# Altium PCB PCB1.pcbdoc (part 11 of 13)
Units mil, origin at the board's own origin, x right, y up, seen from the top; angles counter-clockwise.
Board outline 5895.51 x 5895.51 mil, 8 copper layers (Top Layer, L2_GND1, L3_SIG1, L4_GND2, L5_PWR, L6_SIG2, L7_GND3, Bottom Layer), stack 63.761 mil thick; 673 components, 558 nets, 2797 pads, 1861 vias.
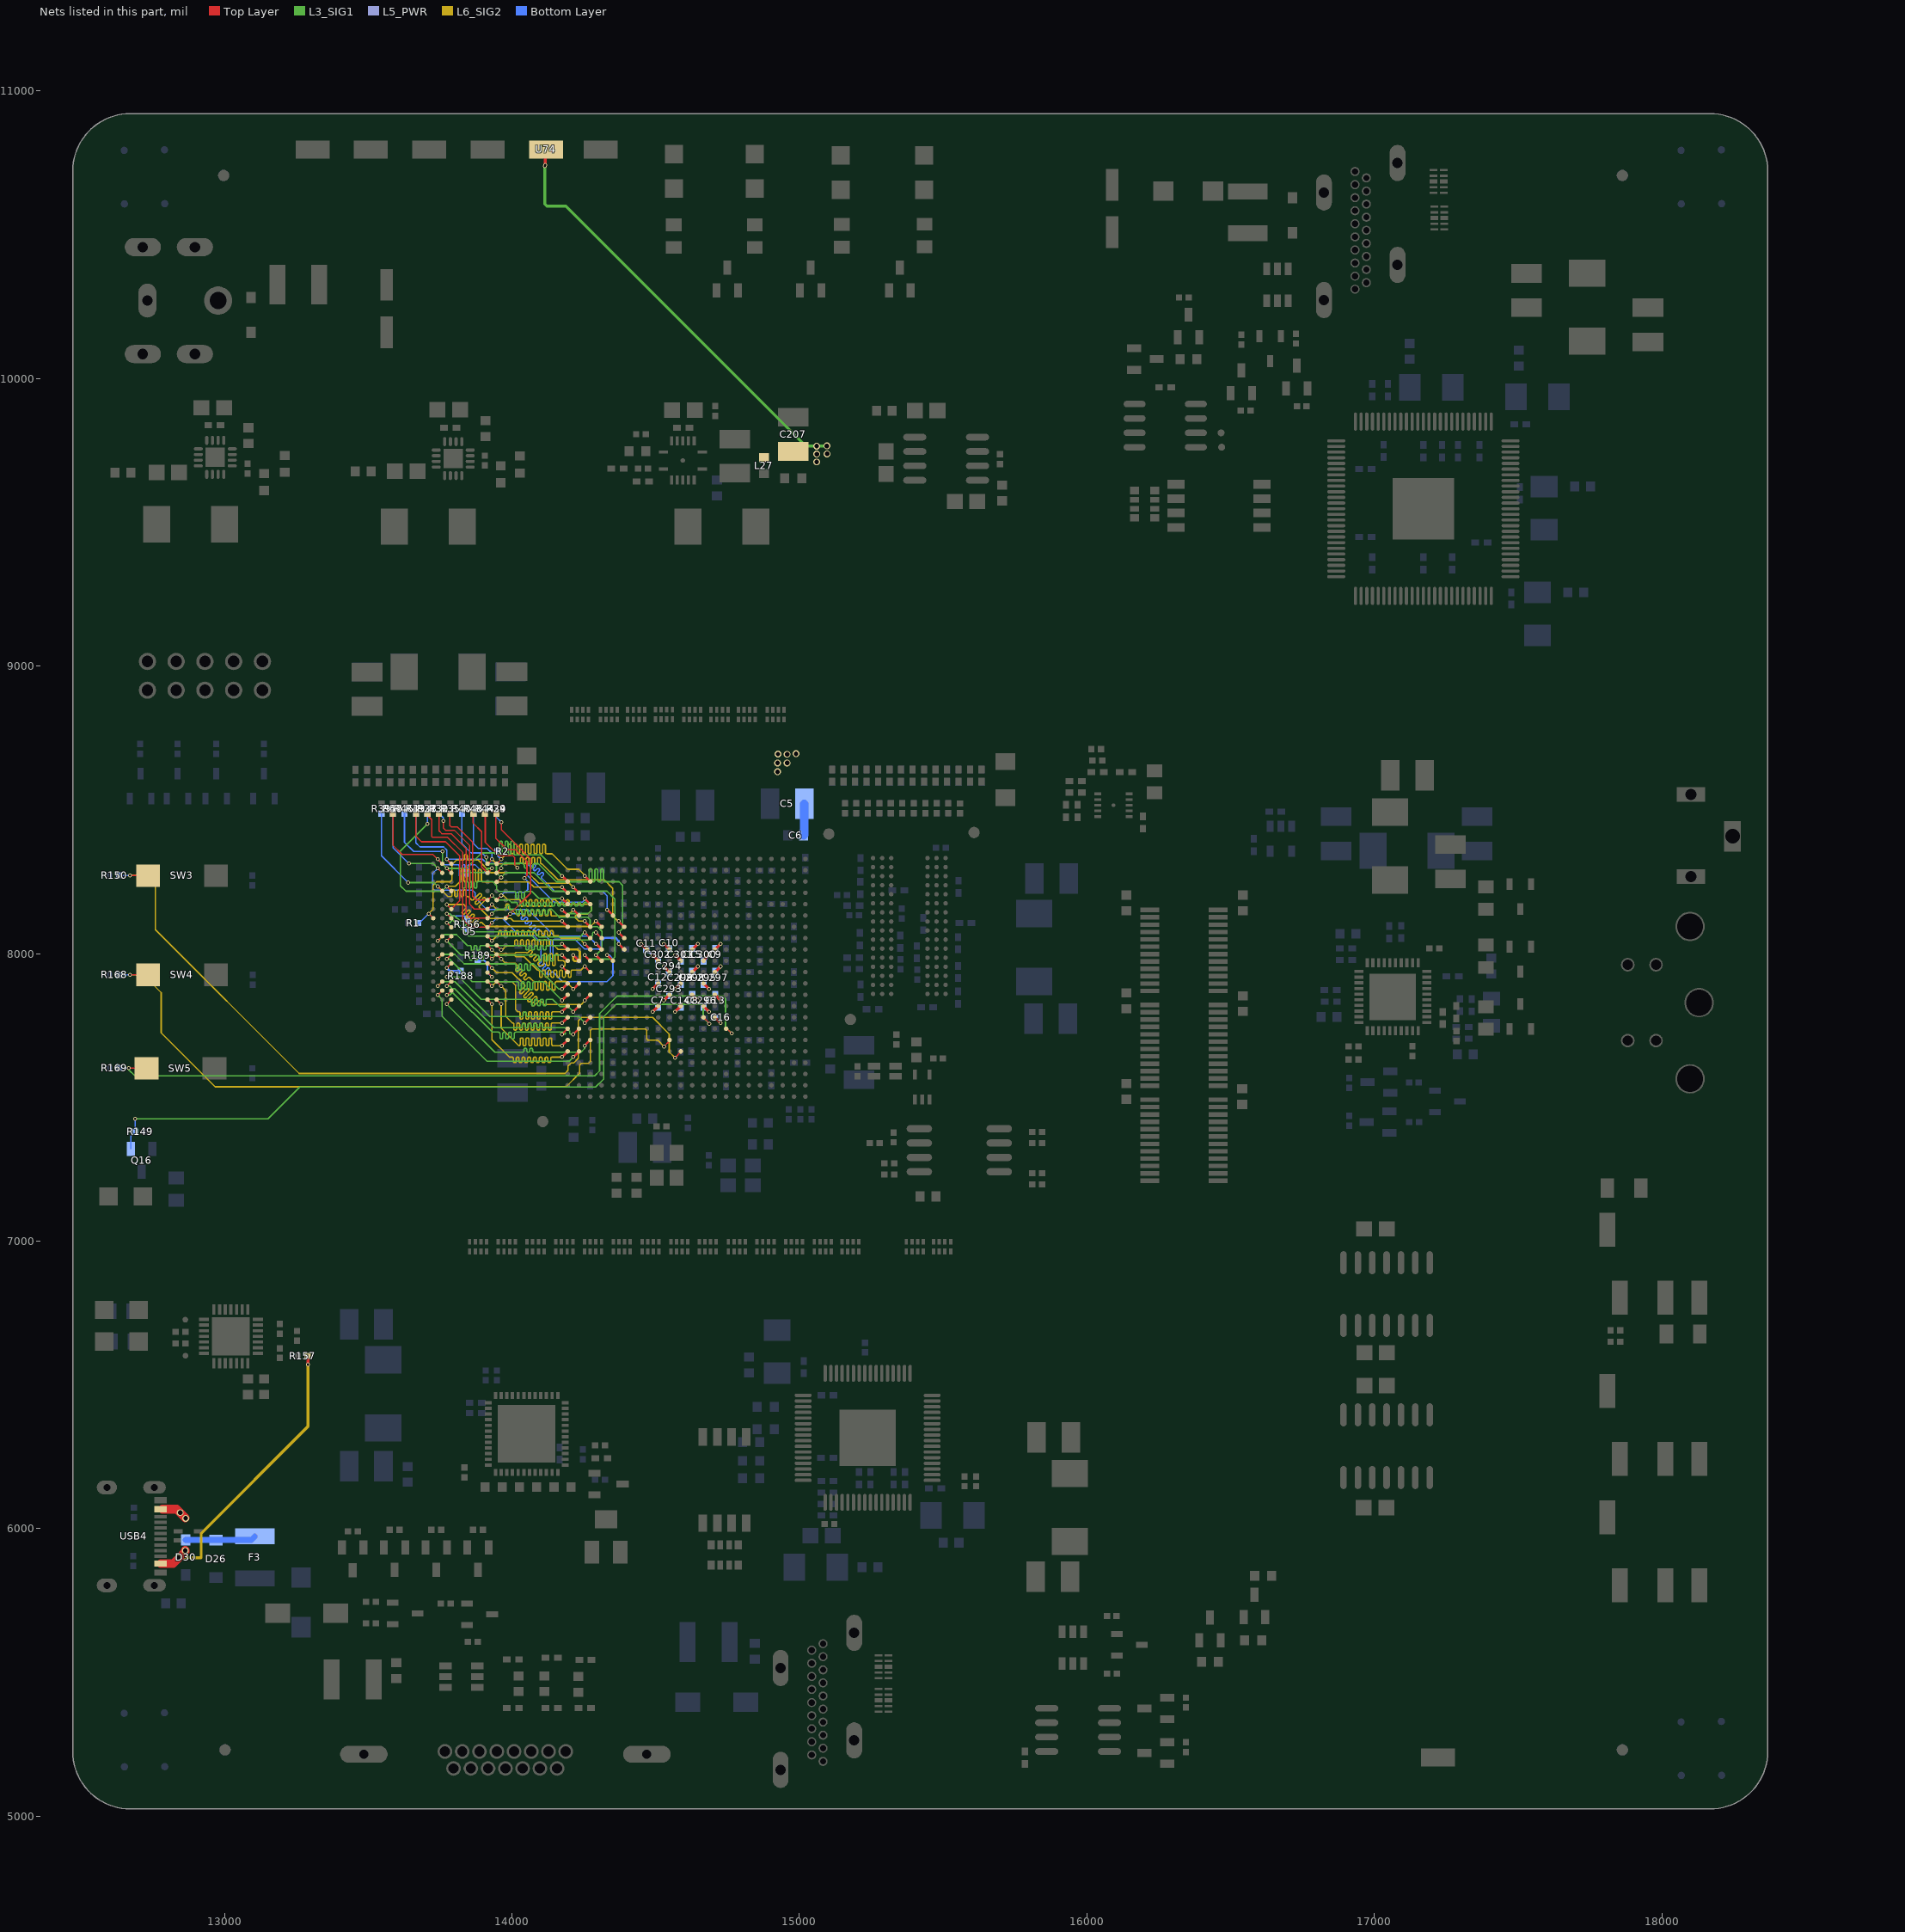
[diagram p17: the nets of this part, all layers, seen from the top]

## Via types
v1: diameter 23.62, hole 15.75, Top Layer to Bottom Layer, 621 vias
v2: diameter 13.8, hole 7.9, Top Layer to Bottom Layer, 567 vias
v3: diameter 13.78, hole 7.87, Top Layer to Bottom Layer, 529 vias
v4: diameter 13.78, hole 7.9, Top Layer to Bottom Layer, 114 vias
v5: diameter 15.75, hole 7.87, Top Layer to Bottom Layer, 16 vias
v6: diameter 24, hole 12, Top Layer to Bottom Layer, 10 vias
v7: diameter 11.81, hole 7.87, Top Layer to Bottom Layer, 4 vias

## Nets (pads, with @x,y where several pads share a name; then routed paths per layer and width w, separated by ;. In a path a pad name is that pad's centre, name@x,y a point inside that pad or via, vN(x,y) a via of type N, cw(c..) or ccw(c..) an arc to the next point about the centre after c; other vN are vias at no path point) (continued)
UP_A5: R40.1 U5.P2 U8.K3 | length 1120.5
  Top Layer w4.7: U5.P2@13946.85,8249.23 v2(13962.59,8264.98)
  Top Layer w7.9: v2(14253.04,7994.73) U8.K3@14272.71,7975.06
  L3_SIG1 w5: v3(13911.36,8335) 13911.36,8319 13918.36,8312 13942.36,8312 13946.36,8308 13946.36,8281.21 v2(13962.59,8264.98) 13978.85,8281.23 14077.44,8281.23 14141.74,8216.93 14330.9,8216.93 14358.3,8189.53 14358.3,7988.4 14350.8,7980.91 14266.86,7980.91 v2(14253.04,7994.73)
  Bottom Layer w4.7: R40.1@13826.36,8486.96 13826.36,8382 13858.36,8350 13896.36,8350 v3(13911.36,8335)
UP_A6: R47.1 U5.R8 U8.J4 | length 1090.5
  Top Layer w4.7: v2(13742.12,8296.47) U5.R8@13757.87,8280.72
  Top Layer w7.9: v2(14292.41,8034.1) U8.J4@14312.08,8014.43
  L3_SIG1 w5: v3(13642.36,8313) 13725.59,8313 v2(13742.12,8296.47)
  Bottom Layer w4.7: R47.1@13586.36,8486.96 13586.36,8369 v3(13642.36,8313) ; v2(13742.12,8296.47) 13723.81,8278.15 13723.81,8224.74 13728.02,8220.53 13862.63,8220.53 13872.74,8210.42 13872.74,8193.68 13913.5,8152.91 14055.84,8152.91 14148.13,8060.62 14265.89,8060.62 v2(14292.41,8034.1)
UP_A7: R44.1 U5.R2 U8.H6 | length 1263.4
  Top Layer w4.7: R44.1@13906.36,8486.96 13907.36,8485.96 13907.36,8387 13953.43,8340.92 14002.95,8340.92 14009.36,8334.51 14009.36,8308 v3(14019.36,8298) ; U5.R2@13946.85,8280.72 v2(13962.59,8296.47)
  Top Layer w7.9: v2(14371.15,8073.47) U8.H6@14390.82,8053.8
  L3_SIG1 w5: v2(13962.59,8296.47) 13962.59,8304.44 13972.37,8314.22 14036.83,8314.22 14043.58,8307.47 14043.58,8302.15 ccw(c14048.58,8302.15) 14053.58,8302.15 14053.58,8307.47 cw(c14058.58,8307.47) 14063.58,8307.47 14063.58,8302.15 ccw(c14068.58,8302.15) 14073.58,8302.15 14073.58,8307.47 cw(c14078.58,8307.47) 14078.58,8312.47 14092.31,8312.47 14155.08,8249.7 14263.59,8249.7 ccw(c14263.59,8254.7) 14268.59,8254.7 14268.59,8289.55 cw(c14273.59,8289.55) 14278.59,8289.55 14278.59,8254.7 ccw(c14283.59,8254.7) 14288.59,8254.7 14288.59,8289.55 cw(c14293.59,8289.55) 14298.59,8289.55 14298.59,8254.7 ccw(c14303.59,8254.7) 14308.59,8254.7 14308.59,8289.55 cw(c14313.59,8289.55) 14318.59,8289.55 14318.59,8254.7 ccw(c14323.59,8254.7) 14323.59,8249.7 14372.66,8249.7 14385.36,8237 14385.36,8087.68 v2(14371.15,8073.47) ; 14003.34,8314.01 v3(14019.36,8298)
  Bottom Layer w4.7: v3(14019.36,8298) v3@14019.36,8301
UP_A8: R50.1 U5.T8 U8.E3 | length 1069.8
  Top Layer w4.7: R50.1@13586.36,8486.96 13586.36,8377 13618.36,8345 13725.09,8345 v2(13742.12,8327.97) U5.T8@13757.87,8312.22
  Top Layer w7.9: v2(14253.04,8191.57) U8.E3@14272.71,8171.9
  Bottom Layer w4.7: v2(13742.12,8327.97) 13760.76,8309.33 13812.12,8309.33 cw(c13812.12,8304.33) 13817.12,8304.33 13817.12,8271.86 ccw(c13822.12,8271.86) 13827.12,8271.86 13827.12,8304.33 cw(c13832.12,8304.33) 13837.12,8304.33 13837.12,8271.86 ccw(c13842.12,8271.86) 13847.12,8271.86 13847.12,8304.33 cw(c13852.12,8304.33) 13852.12,8309.33 13871.32,8309.33 13898.44,8282.21 14043.22,8282.21 14146.7,8178.72 14245.14,8178.72 14253.04,8186.62 v2(14253.04,8191.57)
UP_A9: R45.1 U5.R3 U8.E1 | length 1000.6
  Top Layer w4.7: R45.1@13866.36,8486.96 13865.36,8485.96 13865.36,8453.37 13894.36,8424.37 13894.36,8301.71 U5.R3@13915.35,8280.72 v2(13931.09,8296.47)
  Top Layer w7.9: v2(14174.29,8191.57) U8.E1@14193.96,8171.9
  L3_SIG1 w5: 13828.39,8245.17 ccw(c13823.39,8245.18) 13823.39,8250.18 13819.59,8253.97 13819.59,8273.91 13827.74,8282.05 13901.51,8282.05 13915.93,8296.47 v2(13931.09,8296.47) ; 13828.39,8245.17 13828.38,8232.68 ccw(c13833.38,8232.68) 13838.38,8232.68 13838.39,8245.17 cw(c13843.39,8245.17) 13848.39,8245.17 13848.38,8232.68 ccw(c13853.38,8232.67) 13858.38,8232.67 13858.39,8245.17 cw(c13863.39,8245.17) 13868.39,8245.17 13868.38,8232.67 ccw(c13873.38,8232.67) 13878.38,8232.67 13878.39,8245.17 cw(c13883.39,8245.17) 13883.39,8250.17 13933.49,8250.17 13947.54,8236.12 13947.54,8223.05 13954.35,8216.24 14008.61,8216.24 cw(c14008.61,8211.24) 14013.61,8211.24 14013.61,8195.7 ccw(c14018.61,8195.7) 14023.61,8195.7 14023.61,8211.24 cw(c14028.61,8211.24) 14033.61,8211.24 14033.61,8195.7 ccw(c14038.61,8195.7) 14043.61,8195.7 14043.61,8211.24 cw(c14048.61,8211.24) 14048.61,8216.24 14069.36,8216.24 14093.69,8191.91 14173.95,8191.91 v2(14174.29,8191.57)
UP_A10: R33.1 U5.L7 U8.G4 | length 1236.7
  Top Layer w4.7: R33.1@13666.36,8486.96 13666.36,8408 13685.36,8389 13768.77,8389 13818.36,8339.42 13818.36,8183.73 U5.L7@13789.37,8154.74 v2(13773.62,8170.48)
  Top Layer w7.9: v2(14292.41,8112.84) U8.G4@14312.08,8093.16
  L6_SIG2 w5: v2(13773.62,8170.48) 13833.18,8170.48 13839.56,8164.1 cw(c13836.03,8160.56) 13839.56,8157.03 13828.36,8145.82 ccw(c13831.89,8142.28) 13835.43,8138.75 13846.63,8149.95 cw(c13850.17,8146.42) 13853.71,8142.88 13842.5,8131.68 ccw(c13846.03,8128.14) 13849.57,8124.6 13860.78,8135.81 cw(c13864.31,8132.28) 13867.85,8128.74 13856.64,8117.53 ccw(c13860.18,8114) 13863.71,8110.46 13874.92,8121.67 cw(c13878.45,8118.13) 13881.99,8114.6 13870.78,8103.39 ccw(c13874.32,8099.86) 13877.85,8096.32 13889.06,8107.53 cw(c13892.6,8103.99) 13896.13,8107.53 13909.38,8094.28 14273.84,8094.28 v2(14292.41,8112.84)
UP_A11: R46.1 U5.R7 U8.C1 | length 1074.5
  Top Layer w4.7: v2(13773.62,8296.47) U5.R7@13789.37,8280.72
  Top Layer w7.9: v2(14174.29,8270.32) U8.C1@14193.96,8250.65
  L3_SIG1 w5: v3(13758.36,8355) 13758.36,8311.73 v2(13773.62,8296.47) 13840.82,8296.47 13894.36,8350 13945.05,8350 13951.5,8343.55 ccw(c13951.5,8348.55) 13956.5,8348.55 13956.5,8385.92 cw(c13961.5,8385.92) 13966.5,8385.92 13966.5,8348.55 ccw(c13971.5,8348.55) 13976.5,8348.55 13976.5,8385.92 cw(c13981.5,8385.92) 13986.5,8385.92 13986.5,8348.55 ccw(c13991.5,8348.55) 13996.5,8348.55 13996.5,8385.92 cw(c14001.5,8385.92) 14006.5,8385.92 14006.5,8348.55 ccw(c14011.5,8348.55) 14011.5,8343.55 14101.05,8343.55 v2(14174.29,8270.32)
  Bottom Layer w4.7: R46.1@13626.36,8486.96 13626.36,8387 13658.36,8355 v3(13758.36,8355)
UP_A12: R38.1 U5.N7 U8.D1 | length 1243.6
  Top Layer w4.7: v2(13773.62,8233.48) U5.N7@13789.37,8217.73
  Top Layer w7.9: v2(14174.29,8230.95) U8.D1@14193.96,8211.27
  L3_SIG1 w5: v3(13706.36,8451) 13612.36,8357 13612.36,8236 13631.36,8217 13757.15,8217 v2(13773.62,8233.48)
  L6_SIG2 w5: v2(13773.62,8233.48) 13774.44,8234.3 13803.58,8234.3 13818.74,8249.46 ccw(c13818.74,8254.46) 13823.74,8254.46 13823.74,8287.84 cw(c13828.74,8287.84) 13833.74,8287.84 13833.74,8254.46 ccw(c13838.74,8254.46) 13843.74,8254.46 13843.74,8287.84 cw(c13848.74,8287.84) 13853.74,8287.84 13853.74,8254.46 ccw(c13858.74,8254.46) 13863.74,8254.46 13863.74,8287.84 cw(c13868.74,8287.84) 13873.74,8287.84 13873.74,8254.46 ccw(c13878.74,8254.46) 13883.74,8254.46 13883.74,8287.84 cw(c13888.74,8287.84) 13893.74,8287.84 13893.74,8254.46 ccw(c13898.74,8254.46) 13898.74,8249.46 14058.14,8249.46 14076.65,8230.95 v2(14174.29,8230.95)
  Bottom Layer w4.7: v3(13706.36,8451) R38.1@13706.36,8486.96
UP_A13: R48.1 U5.T3 U8.G6 | length 985.5
  Top Layer w4.7: U5.T3@13915.35,8312.22 v2(13931.09,8327.97)
  Top Layer w7.9: v2(14371.15,8112.84) U8.G6@14390.82,8093.16
  L6_SIG2 w5: v2(13931.09,8327.97) 13947.19,8311.86 14024.13,8311.86 ccw(c14024.13,8316.86) 14029.13,8316.86 14029.13,8329.47 cw(c14034.13,8329.47) 14039.13,8329.47 14039.13,8316.86 ccw(c14044.13,8316.86) 14049.13,8316.86 14049.13,8329.47 cw(c14054.13,8329.47) 14059.13,8329.47 14059.13,8316.86 ccw(c14064.13,8316.86) 14069.13,8316.86 14069.13,8329.47 cw(c14074.13,8329.47) 14079.13,8329.47 14079.13,8316.86 ccw(c14084.13,8316.86) 14089.13,8316.86 14089.13,8329.47 cw(c14094.13,8329.47) 14099.13,8329.47 14099.13,8316.86 ccw(c14104.13,8316.86) 14104.13,8311.86 14104.98,8311.86 14160.43,8256.41 14321.57,8256.41 14350.95,8227.03 14350.95,8130.82 14368.93,8112.84 v2(14371.15,8112.84)
  Bottom Layer w4.7: R48.1@13866.36,8486.96 13866.36,8383 13883.36,8366 13913.36,8366 13930.36,8349 13930.36,8328.7 v2(13931.09,8327.97)
UP_A14: R49.1 U5.T7 U8.F5 | length 1034.6
  Top Layer w4.7: v2(13773.62,8327.97) U5.T7@13789.37,8312.22
  Top Layer w7.9: v2(14331.79,8152.21) U8.F5@14351.46,8132.53
  Bottom Layer w4.7: R49.1@13666.36,8486.96 13666.36,8385 13680.36,8371 13762.36,8371 13773.36,8360 13773.36,8328.23 v2(13773.62,8327.97) ; v2@13773.39,8328.34 13897.46,8328.34 13911.86,8313.94 14052.15,8313.94 14062.01,8304.08 ccw(c14065.55,8307.62) 14069.08,8304.08 14073.75,8308.75 cw(c14077.28,8305.21) 14080.82,8301.68 14076.15,8297.01 ccw(c14079.69,8293.48) 14083.23,8289.94 14087.89,8294.61 cw(c14091.43,8291.07) 14094.96,8287.53 14090.3,8282.87 ccw(c14093.83,8279.33) 14097.37,8275.8 14102.03,8280.46 cw(c14105.57,8276.93) 14109.1,8273.39 14104.44,8268.73 ccw(c14107.97,8265.19) 14104.44,8261.66 14149.72,8216.38 14316.07,8216.38 14331.63,8200.82 v2@14331.63,8152.66
UP_BA0: R34.1 U5.M2 U8.G3 | length 1189.9
  Top Layer w4.7: R34.1@13946.36,8486.96 13944.36,8484.96 13944.36,8401 13984.36,8361 14012.36,8361 14052.36,8321 14052.36,8272 v3(14043.36,8263) ; U5.M2@13946.85,8186.24 v2(13962.59,8201.99)
  Top Layer w7.9: v2(14253.04,8112.84) U8.G3@14272.71,8093.16
  L6_SIG2 w5: v2(13962.59,8201.99) 13970.78,8201.99 13985.02,8187.75 14024.81,8187.75 cw(c14024.81,8182.75) 14029.81,8182.75 14029.81,8169.4 ccw(c14034.81,8169.4) 14039.81,8169.4 14039.81,8182.75 cw(c14044.81,8182.75) 14049.81,8182.75 14049.81,8169.4 ccw(c14054.81,8169.4) 14059.81,8169.4 14059.81,8182.75 cw(c14064.81,8182.75) 14069.81,8182.75 14069.81,8169.4 ccw(c14074.81,8169.4) 14079.81,8169.4 14079.81,8182.75 cw(c14084.81,8182.75) 14089.81,8182.75 14089.81,8169.4 ccw(c14094.81,8169.4) 14099.81,8169.4 14099.81,8182.75 cw(c14104.81,8182.75) 14109.81,8182.75 14109.81,8169.4 ccw(c14114.81,8169.4) 14119.81,8169.4 14119.81,8182.75 cw(c14124.81,8182.75) 14129.81,8182.75 14129.81,8169.4 ccw(c14134.81,8169.4) 14139.81,8169.4 14139.81,8182.75 cw(c14144.81,8182.75) 14144.81,8187.75 14150.2,8187.75 14166.45,8171.49 14184.06,8171.49 ccw(c14184.06,8176.49) 14189.06,8176.49 14189.06,8182.15 cw(c14194.06,8182.15) 14199.06,8182.15 14199.06,8176.49 ccw(c14204.06,8176.49) 14204.06,8171.49 14272.05,8171.49 14275.53,8168.01 14275.53,8149.06 14264.47,8138 14227.5,8138 14220.55,8131.05 14220.55,8125.36 14233.07,8112.84 v2(14253.04,8112.84)
  Bottom Layer w4.7: v2(13962.59,8201.99) 13974.27,8213.66 14046.02,8213.66 14054.36,8222 14055.36,8222 14055.36,8251 v3(14043.36,8263)
UP_BA1: R39.1 U5.N8 U8.G1 | length 1166.6
  Top Layer w4.7: v2(13742.12,8233.48) U5.N8@13757.87,8217.73
  Top Layer w7.9: v2(14174.29,8112.84) U8.G1@14193.96,8093.16
  L3_SIG1 w5: v3(13639.36,8247) 13728.6,8247 v2(13742.12,8233.48)
  L6_SIG2 w5: v2(13742.12,8233.48) 13777.48,8198.11 13786.27,8198.11 ccw(c13786.27,8203.11) 13791.27,8203.11 13791.27,8216.33 cw(c13796.27,8216.33) 13801.27,8216.33 13801.27,8203.11 ccw(c13806.27,8203.11) 13811.27,8203.11 13811.27,8216.33 cw(c13816.27,8216.33) 13821.27,8216.33 13821.27,8203.11 ccw(c13826.27,8203.11) 13831.27,8203.11 13831.27,8216.33 cw(c13836.27,8216.33) 13841.27,8216.33 13841.27,8203.11 ccw(c13846.27,8203.11) 13846.27,8198.11 13848.63,8198.11 13859.3,8187.45 ccw(c13862.83,8190.99) 13866.37,8187.45 13886.01,8207.1 cw(c13889.55,8203.56) 13893.08,8200.02 13873.44,8180.38 ccw(c13876.98,8176.84) 13880.51,8173.31 13900.16,8192.95 cw(c13903.69,8189.42) 13907.23,8185.88 13887.58,8166.24 ccw(c13891.12,8162.7) 13887.58,8159.17 13924.31,8122.44 13996.19,8122.44 14005.35,8113.28 14173.85,8113.28 v2(14174.29,8112.84)
  Bottom Layer w4.7: R39.1@13546.36,8486.96 13546.36,8340 v3(13639.36,8247)
UP_BA2: R35.1 U5.M3 U8.F1 | length 1129.4
  Top Layer w4.7: R35.1@13786.36,8486.96 13784.36,8484.96 13784.36,8445 13788.36,8441 13809.41,8441 13863.36,8387.05 13863.36,8200 13877.12,8186.24 U5.M3@13915.35,8186.24 v2(13931.09,8201.99)
  Top Layer w7.9: v2(14174.29,8152.21) U8.F1@14193.96,8132.53
  L3_SIG1 w5: v2(13931.09,8201.99) 13947.21,8185.87 13990.64,8185.87 13998.54,8177.97 14014.14,8177.97 cw(c14014.14,8172.97) 14019.14,8172.97 14019.14,8170.27 ccw(c14024.14,8170.27) 14029.14,8170.27 14029.14,8172.97 cw(c14034.14,8172.97) 14039.14,8172.97 14039.14,8170.27 ccw(c14044.14,8170.27) 14049.14,8170.27 14049.14,8172.97 cw(c14054.14,8172.97) 14059.14,8172.97 14059.14,8170.27 ccw(c14064.14,8170.27) 14069.14,8170.27 14069.14,8172.97 cw(c14074.14,8172.97) 14079.14,8172.97 14079.14,8170.27 ccw(c14084.14,8170.27) 14089.14,8170.27 14089.14,8172.97 cw(c14094.14,8172.97) 14099.14,8172.97 14099.14,8170.27 ccw(c14104.14,8170.27) 14109.14,8170.27 14109.14,8172.97 cw(c14114.14,8172.97) 14119.14,8172.97 14119.14,8170.27 ccw(c14124.14,8170.27) 14129.14,8170.27 14129.14,8172.97 cw(c14134.14,8172.97) 14139.14,8172.97 14139.14,8170.27 ccw(c14144.14,8170.27) 14149.14,8170.27 14149.14,8172.97 cw(c14154.14,8172.97) 14159.14,8172.97 14159.14,8170.27 ccw(c14164.14,8170.27) 14169.14,8170.27 14169.14,8172.97 cw(c14174.14,8172.97) 14179.14,8172.97 14179.14,8170.27 ccw(c14184.14,8170.27) 14189.14,8170.27 14189.14,8172.97 cw(c14194.14,8172.97) 14199.14,8172.97 14199.14,8170.27 ccw(c14204.14,8170.27) 14209.14,8170.27 14209.14,8172.97 cw(c14214.14,8172.97) 14219.14,8172.97 14219.14,8170.27 ccw(c14224.14,8170.27) 14229.14,8170.27 14229.14,8172.97 cw(c14234.14,8172.97) 14239.14,8172.97 14239.14,8170.27 ccw(c14244.14,8170.27) 14249.14,8170.27 14249.14,8172.97 cw(c14254.14,8172.97) 14254.14,8177.97 14260.79,8177.97 14277.22,8161.54 14277.22,8150.8 14265.42,8139 14187.49,8139 v2(14174.29,8152.21)
UP_CAS: R30.1 U5.K3 U8.K4 | length 1245.6
  Top Layer w4.7: R30.1@13746.36,8486.96 13746.36,8427 13756.36,8417 13788.45,8417 13841.36,8364.1 13841.36,8139 13857.12,8123.24 U5.K3@13915.35,8123.24 v2(13931.09,8138.98)
  Top Layer w7.9: v2(14292.41,7994.73) U8.K4@14312.08,7975.06
  L3_SIG1 w5: v2(13931.09,8138.98) 13946.11,8154 13977.33,8154 ccw(c13977.33,8159) 13982.33,8159 13982.33,8163.53 cw(c13987.33,8163.53) 13992.33,8163.53 13992.33,8159 ccw(c13997.33,8159) 13997.33,8154 14010.61,8154 cw(c14010.61,8149) 14015.61,8149 14015.61,8140.88 ccw(c14020.61,8140.88) 14025.61,8140.88 14025.61,8149 cw(c14030.61,8149) 14035.61,8149 14035.61,8140.88 ccw(c14040.61,8140.88) 14045.61,8140.88 14045.61,8149 cw(c14050.61,8149) 14055.61,8149 14055.61,8140.88 ccw(c14060.61,8140.88) 14065.61,8140.88 14065.61,8149 cw(c14070.61,8149) 14075.61,8149 14075.61,8140.88 ccw(c14080.61,8140.88) 14085.61,8140.88 14085.61,8149 cw(c14090.61,8149) 14095.61,8149 14095.61,8140.88 ccw(c14100.61,8140.88) 14105.61,8140.88 14105.61,8149 cw(c14110.61,8149) 14115.61,8149 14115.61,8140.88 ccw(c14120.61,8140.88) 14125.61,8140.88 14125.61,8149 cw(c14130.61,8149) 14130.61,8154 14137.94,8154 14165.73,8126.21 14263.68,8126.21 14272.23,8117.66 14272.23,8099.97 14278.55,8093.65 14297.5,8093.65 14313.62,8077.53 14313.62,8015.94 v2(14292.41,7994.73)
  L3_SIG1 w7.9: 14165.73,8126.21 14165.85,8126.09
UP_CK+: R156.1 U5.J7 U8.H4 | length 703.9
  Top Layer w4.7: v2(13773.62,8107.49) U5.J7@13789.37,8091.75
  Top Layer w6.2: v2(14292.41,8073.47) U8.H4@14312.08,8053.8
  L3_SIG1 w4.2: v2(13773.62,8107.49) 13783.62,8107.49 13791.77,8115.64 13794.87,8115.64 13849.36,8061.15 14071.21,8061.15 14084.64,8047.72 14266.16,8047.72 14280.32,8061.88 14280.32,8071.28 14282.51,8073.47 v2(14292.41,8073.47)
  Bottom Layer w4: v2(13773.62,8107.49) 13783.62,8107.49 13791.77,8115.64 13800.09,8115.64 13831.07,8084.66 R156.1@13844.8,8084.66
UP_CK-: R156.2 U5.K7 U8.H3 | length 709
  Top Layer w4.7: v2(13773.62,8138.98) U5.K7@13789.37,8123.24
  Top Layer w6.2: v2(14253.04,8073.47) U8.H3@14272.71,8053.8
  L3_SIG1 w4.2: v2(13773.62,8138.98) 13783.62,8138.98 13791.77,8130.84 13801.16,8130.84 13818.13,8113.88 ccw(c13821.66,8117.41) 13825.2,8113.88 13828.07,8116.75 cw(c13831.61,8113.22) 13835.14,8109.68 13832.27,8106.81 ccw(c13835.8,8103.27) 13839.34,8099.74 13842.21,8102.61 cw(c13845.75,8099.08) 13849.29,8095.54 13846.41,8092.66 ccw(c13849.95,8089.13) 13846.41,8085.59 13856,8076 14077.01,8076 14095.01,8058 14237.05,8058 14252.52,8073.47 v2(14253.04,8073.47)
  Bottom Layer w4: v2(13773.62,8138.98) 13783.62,8138.98 13791.77,8130.84 13837.16,8130.84 13851.1,8116.9 13851.1,8112.22 13844.8,8118.51 R156.2@13844.8,8118.74
UP_CKE: R1.1 U5.K9 U8.D2 | length 831.2
  Top Layer w4.7: v2(13710.63,8138.98) U5.K9@13726.38,8123.24
  Top Layer w7.9: v2(14213.67,8230.95) U8.D2@14233.34,8211.27
  L6_SIG2 w5: v2(13710.63,8138.98) 13725.61,8153.97 13725.61,8237.22 13738.41,8250.02 13786.75,8250.02 ; 13786.87,8250.13 13792.01,8255.28 13792.01,8309.67 13807.39,8325.04 13829.61,8325.04 ccw(c13829.61,8330.04) 13834.61,8330.04 13834.61,8339.71 cw(c13839.61,8339.71) 13844.61,8339.71 13844.61,8330.04 ccw(c13849.61,8330.04) 13849.61,8325.04 13882.91,8325.04 13926.55,8281.4 14056.9,8281.4 14093.55,8244.75 14199.87,8244.75 v2(14213.67,8230.95)
  Bottom Layer w4.7: R1.1@13673.36,8106.34 13677.99,8106.34 v2(13710.63,8138.98)
UP_D0: U5.E3 U8.N3 | length 652.6
  Top Layer w4.7: U5.E3@13915.35,7965.76 v2(13931.09,7950.02)
  Top Layer w7.9: v2(14253.04,7837.27) U8.N3@14272.71,7856.94
  L6_SIG2 w5: v2(13931.09,7950.02) 13947.11,7934 14001.36,7934 14043.8,7891.56 cw(c14040.26,7888.02) 14043.8,7884.49 14028.32,7869.01 ccw(c14031.85,7865.47) 14035.39,7861.93 14050.87,7877.42 cw(c14054.4,7873.88) 14057.94,7870.35 14042.46,7854.86 ccw(c14045.99,7851.33) 14049.53,7847.79 14065.01,7863.27 cw(c14068.55,7859.74) 14072.08,7856.2 14056.6,7840.72 ccw(c14060.14,7837.19) 14063.67,7833.65 14079.15,7849.13 cw(c14082.69,7845.6) 14086.22,7842.06 14070.74,7826.58 ccw(c14074.28,7823.04) 14077.81,7819.51 14093.3,7834.99 cw(c14096.83,7831.46) 14100.37,7834.99 14112,7823.36 14241.71,7823.36 14253.04,7834.68 v2(14253.04,7837.27)
UP_D1: U5.F7 U8.N1 | length 650.5
  Top Layer w4.7: v2(13773.62,7981.52) U5.F7@13789.37,7997.26
  Top Layer w7.9: v2(14174.29,7837.27) U8.N1@14193.96,7856.94
  L3_SIG1 w5: v2(13773.62,7981.52) 13782.25,7981.52 13861.7,7902.06 14018.12,7902.06 cw(c14018.12,7897.06) 14023.12,7897.06 14023.12,7879.44 ccw(c14028.12,7879.44) 14033.12,7879.44 14033.12,7897.06 cw(c14038.12,7897.06) 14043.12,7897.06 14043.12,7879.44 ccw(c14048.12,7879.44) 14053.12,7879.44 14053.12,7897.06 cw(c14058.12,7897.06) 14063.12,7897.06 14063.12,7879.44 ccw(c14068.12,7879.44) 14073.12,7879.44 14073.12,7897.06 cw(c14078.12,7897.06) 14078.12,7902.06 14109.49,7902.06 v2(14174.29,7837.27)
UP_D2: U5.F2 U8.M2 | length 632.2
  Top Layer w4.7: U5.F2@13946.85,7997.26 v2(13962.59,7981.52)
  Top Layer w7.9: v2(14213.67,7876.62) U8.M2@14233.34,7896.3
  L6_SIG2 w5: v2(13962.59,7981.52) 13962.84,7981.52 13978.36,7966 14012.36,7966 14020,7958.35 cw(c14016.47,7954.82) 14020,7951.28 14014.62,7945.9 ccw(c14018.15,7942.36) 14021.69,7938.83 14027.07,7944.21 cw(c14030.61,7940.68) 14034.15,7937.14 14028.76,7931.75 ccw(c14032.29,7928.22) 14035.83,7924.68 14041.22,7930.07 cw(c14044.75,7926.53) 14048.29,7923 14042.9,7917.61 ccw(c14046.44,7914.08) 14049.97,7910.54 14055.36,7915.93 cw(c14058.89,7912.39) 14062.43,7915.93 14075.36,7903 cw(c14075.36,7898) 14080.36,7898 14080.36,7877.75 ccw(c14085.36,7877.75) 14090.36,7877.75 14090.36,7898 cw(c14095.36,7898) 14100.36,7898 14100.36,7877.75 ccw(c14105.36,7877.75) 14110.36,7877.75 14110.36,7898 cw(c14115.36,7898) 14120.36,7898 14120.36,7877.75 ccw(c14125.36,7877.75) 14130.36,7877.75 14130.36,7898 cw(c14135.36,7898) 14140.36,7898 14140.36,7877.75 ccw(c14145.36,7877.75) 14150.36,7877.75 14150.36,7898 cw(c14155.36,7898) 14155.36,7903 14187.29,7903 v2(14213.67,7876.62)
UP_D3: U5.F8 U8.M1 | length 652.6
  Top Layer w4.7: v2(13742.12,7981.52) U5.F8@13757.87,7997.26
  Top Layer w7.9: v2(14174.29,7876.62) U8.M1@14193.96,7896.3
  L3_SIG1 w5: v2(13742.12,7981.52) 13757.61,7997 13801.36,7997 13834.02,7964.34 14009.15,7964.34 cw(c14009.15,7959.34) 14014.15,7959.34 14014.15,7946.04 ccw(c14019.15,7946.04) 14024.15,7946.04 14024.15,7959.34 cw(c14029.15,7959.34) 14034.15,7959.34 14034.15,7946.04 ccw(c14039.15,7946.04) 14044.15,7946.04 14044.15,7959.34 cw(c14049.15,7959.34) 14054.15,7959.34 14054.15,7946.04 ccw(c14059.15,7946.04) 14064.15,7946.04 14064.15,7959.34 cw(c14069.15,7959.34) 14069.15,7964.34 14075.53,7964.34 14163.24,7876.62 v2(14174.29,7876.62)
UP_D4: U5.H3 U8.J3 | length 659.1
  Top Layer w4.7: U5.H3@13915.35,8060.25 v2(13931.09,8044.51)
  Top Layer w7.9: v2(14253.04,8034.1) U8.J3@14272.71,8014.43
  L6_SIG2 w5: v2(13931.09,8044.51) 13948.59,8062 ccw(c13948.59,8067) 13953.59,8067 13953.59,8074.71 cw(c13958.59,8074.71) 13963.59,8074.71 13963.59,8067 ccw(c13968.59,8067) 13973.59,8067 13973.59,8074.71 cw(c13978.59,8074.71) 13983.59,8074.71 13983.59,8067 ccw(c13988.59,8067) 13993.59,8067 13993.59,8074.71 cw(c13998.59,8074.71) 14003.59,8074.71 14003.59,8067 ccw(c14008.59,8067) 14013.59,8067 14013.59,8074.71 cw(c14018.59,8074.71) 14023.59,8074.71 14023.59,8067 ccw(c14028.59,8067) 14033.59,8067 14033.59,8074.71 cw(c14038.59,8074.71) 14043.59,8074.71 14043.59,8067 ccw(c14048.59,8067) 14053.59,8067 14053.59,8074.71 cw(c14058.59,8074.71) 14063.59,8074.71 14063.59,8067 ccw(c14068.59,8067) 14073.59,8067 14073.59,8074.71 cw(c14078.59,8074.71) 14083.59,8074.71 14083.59,8067 ccw(c14088.59,8067) 14093.59,8067 14093.59,8074.71 cw(c14098.59,8074.71) 14103.59,8074.71 14103.59,8067 ccw(c14108.59,8067) 14113.59,8067 14113.59,8074.71 cw(c14118.59,8074.71) 14123.59,8074.71 14123.59,8067 ccw(c14128.59,8067) 14133.59,8067 14133.59,8074.71 cw(c14138.59,8074.71) 14143.59,8074.71 14143.59,8067 ccw(c14148.59,8067) 14148.59,8062 14161.36,8062 14169.36,8054 14233.14,8054 v2(14253.04,8034.1)
UP_D5: U5.H8 U8.J1 | length 650.8
  Top Layer w4.7: v2(13742.12,8044.51) U5.H8@13757.87,8060.25
  Top Layer w7.9: v2(14174.29,8034.1) U8.J1@14193.96,8014.43
  L3_SIG1 w5: v2(13742.12,8044.51) 13743.86,8044.51 13765.36,8066 13807.36,8066 13845.36,8028 13853.42,8028 cw(c13853.42,8023) 13858.42,8023 13858.42,8015.39 ccw(c13863.42,8015.39) 13868.42,8015.39 13868.42,8023 cw(c13873.42,8023) 13878.42,8023 13878.42,8015.39 ccw(c13883.42,8015.39) 13888.42,8015.39 13888.42,8023 cw(c13893.42,8023) 13893.42,8028 14043.89,8028 cw(c14043.89,8023) 14048.89,8023 14048.89,8017.69 ccw(c14053.89,8017.69) 14058.89,8017.69 14058.89,8023 cw(c14063.89,8023) 14068.89,8023 14068.89,8017.69 ccw(c14073.89,8017.69) 14078.89,8017.69 14078.89,8023 cw(c14083.89,8023) 14088.89,8023 14088.89,8017.69 ccw(c14093.89,8017.69) 14098.89,8017.69 14098.89,8023 cw(c14103.89,8023) 14108.89,8023 14108.89,8017.69 ccw(c14113.89,8017.69) 14118.89,8017.69 14118.89,8023 cw(c14123.89,8023) 14123.89,8028 14168.19,8028 v2(14174.29,8034.1)
UP_D6: U5.G2 U8.K2 | length 644.8
  Top Layer w4.7: U5.G2@13946.85,8028.76 v2(13962.59,8013.02)
  Top Layer w7.9: v2(14213.67,7994.73) U8.K2@14233.34,7975.06
  L6_SIG2 w5: v2(13962.59,8013.02) 13966.39,8013.02 13980.49,8027.12 14005.08,8027.12 ccw(c14005.08,8032.12) 14010.08,8032.12 14010.08,8042.95 cw(c14015.08,8042.95) 14020.08,8042.95 14020.08,8032.12 ccw(c14025.08,8032.12) 14030.08,8032.12 14030.08,8042.95 cw(c14035.08,8042.95) 14040.08,8042.95 14040.08,8032.12 ccw(c14045.08,8032.12) 14050.08,8032.12 14050.08,8042.95 cw(c14055.08,8042.95) 14060.08,8042.95 14060.08,8032.12 ccw(c14065.08,8032.12) 14070.08,8032.12 14070.08,8042.95 cw(c14075.08,8042.95) 14080.08,8042.95 14080.08,8032.12 ccw(c14085.08,8032.12) 14090.08,8032.12 14090.08,8042.95 cw(c14095.08,8042.95) 14100.08,8042.95 14100.08,8032.12 ccw(c14105.08,8032.12) 14110.08,8032.12 14110.08,8042.95 cw(c14115.08,8042.95) 14120.08,8042.95 14120.08,8032.12 ccw(c14125.08,8032.12) 14130.08,8032.12 14130.08,8042.95 cw(c14135.08,8042.95) 14140.08,8042.95 14140.08,8032.12 ccw(c14145.08,8032.12) 14145.08,8027.12 14147.9,8027.12 14160.85,8014.16 14193.71,8014.16
  L6_SIG2 w7.9: 14194.34,8014.79 14193.71,8014.16 14229.44,8014.16 14236.36,8007.25 14236.36,7976.91 14232.99,7973.54 14218.03,7973.54 14212.97,7978.6 14212.97,7994.04 v2(14213.67,7994.73) v2@14213.67,7995.47
UP_D7: U5.H7 U8.K1 | length 652.2
  Top Layer w4.7: v2(13773.62,8044.51) U5.H7@13789.37,8060.25
  Top Layer w7.9: v2(14174.29,7994.73) U8.K1@14193.96,7975.06
  L3_SIG1 w5: v2(13773.62,8044.51) 13823.4,7994.73 13847.32,7994.73 cw(c13847.32,7989.73) 13852.32,7989.73 13852.32,7982.15 ccw(c13857.32,7982.15) 13862.32,7982.15 13862.32,7989.73 cw(c13867.32,7989.73) 13872.32,7989.73 13872.32,7982.15 ccw(c13877.32,7982.15) 13882.32,7982.15 13882.32,7989.73 cw(c13887.32,7989.73) 13892.32,7989.73 13892.32,7982.15 ccw(c13897.32,7982.15) 13902.32,7982.15 13902.32,7989.73 cw(c13907.32,7989.73) 13907.32,7994.73 14089.2,7994.73 cw(c14089.2,7989.73) 14094.2,7989.73 14094.2,7978.59 ccw(c14099.2,7978.59) 14104.2,7978.59 14104.2,7989.73 cw(c14109.2,7989.73) 14114.2,7989.73 14114.2,7978.59 ccw(c14119.2,7978.59) 14124.2,7978.59 14124.2,7989.73 cw(c14129.2,7989.73) 14134.2,7989.73 14134.2,7978.59 ccw(c14139.2,7978.59) 14144.2,7978.59 14144.2,7989.73 cw(c14149.2,7989.73) 14149.2,7994.73 v2(14174.29,7994.73)
UP_D8: U5.D7 U8.P2 | length 652.4
  Top Layer w4.7: v2(13773.62,7918.52) U5.D7@13789.37,7934.27
  Top Layer w7.9: v2(14213.67,7797.9) U8.P2@14233.34,7817.57
  L3_SIG1 w5: v2(13773.62,7918.52) 13816.33,7918.52 13893.47,7841.38 14064.01,7841.38 cw(c14064.01,7836.38) 14069.01,7836.38 14069.01,7823.37 ccw(c14074.01,7823.37) 14079.01,7823.37 14079.01,7836.38 cw(c14084.01,7836.38) 14089.01,7836.38 14089.01,7823.37 ccw(c14094.01,7823.37) 14099.01,7823.37 14099.01,7836.38 cw(c14104.01,7836.38) 14109.01,7836.38 14109.01,7823.37 ccw(c14114.01,7823.37) 14119.01,7823.37 14119.01,7836.38 cw(c14124.01,7836.38) 14124.01,7841.38 14141.56,7841.38 14166.75,7816.19 14195.38,7816.19 v2(14213.67,7797.9)
UP_D9: U5.C3 U8.P1 | length 653.7
  Top Layer w4.7: U5.C3@13915.35,7902.77 v2(13931.09,7887.02)
  Top Layer w7.9: v2(14174.29,7797.9) U8.P1@14193.96,7817.57
  L6_SIG2 w5: v2(13931.09,7887.02) 13946.07,7902 14000.17,7902 14012.76,7889.41 14012.76,7805.8 14020.66,7797.9 14023.46,7797.9 cw(c14023.46,7792.9) 14028.46,7792.9 14028.46,7776.76 ccw(c14033.46,7776.76) 14038.46,7776.76 14038.46,7792.9 cw(c14043.46,7792.9) 14048.46,7792.9 14048.46,7776.76 ccw(c14053.46,7776.76) 14058.46,7776.76 14058.46,7792.9 cw(c14063.46,7792.9) 14068.46,7792.9 14068.46,7776.76 ccw(c14073.46,7776.76) 14078.46,7776.76 14078.46,7792.9 cw(c14083.46,7792.9) 14088.46,7792.9 14088.46,7776.76 ccw(c14093.46,7776.76) 14098.46,7776.76 14098.46,7792.9 cw(c14103.46,7792.9) 14108.46,7792.9 14108.46,7776.76 ccw(c14113.46,7776.76) 14118.46,7776.76 14118.46,7792.9 cw(c14123.46,7792.9) 14128.46,7792.9 14128.46,7776.76 ccw(c14133.46,7776.76) 14138.46,7776.76 14138.46,7792.9 cw(c14143.46,7792.9) 14143.46,7797.9 v2(14174.29,7797.9)
UP_D10: U5.C8 U8.R3 | length 651.2
  Top Layer w4.7: v2(13742.12,7887.02) U5.C8@13757.87,7902.77
  Top Layer w7.9: v2(14253.04,7758.52) U8.R3@14272.71,7778.2
  L3_SIG1 w5: v2(13742.12,7887.02) 13757.1,7902 13802.36,7902 13923.36,7781 14034.94,7781 ccw(c14034.94,7786) 14039.94,7786 14039.94,7792.07 cw(c14044.94,7792.07) 14049.94,7792.07 14049.94,7786 ccw(c14054.94,7786) 14054.94,7781 14232.36,7781 14253.04,7760.32 v2(14253.04,7758.52)
UP_D11: U5.C2 U8.R1 | length 653.6
  Top Layer w4.7: U5.C2@13946.85,7902.77 v2(13962.59,7887.02)
  Top Layer w7.9: v2(14174.29,7758.52) U8.R1@14193.96,7778.2
  L6_SIG2 w5: v2(13962.59,7887.02) 13978.36,7871.26 13978.36,7782 14001.84,7758.52 cw(c14001.84,7753.52) 14006.84,7753.52 14006.84,7738.78 ccw(c14011.84,7738.78) 14016.84,7738.78 14016.84,7753.52 cw(c14021.84,7753.52) 14026.84,7753.52 14026.84,7738.78 ccw(c14031.84,7738.78) 14036.84,7738.78 14036.84,7753.52 cw(c14041.84,7753.52) 14046.84,7753.52 14046.84,7738.78 ccw(c14051.84,7738.78) 14056.84,7738.78 14056.84,7753.52 cw(c14061.84,7753.52) 14066.84,7753.52 14066.84,7738.78 ccw(c14071.84,7738.78) 14076.84,7738.78 14076.84,7753.52 cw(c14081.84,7753.52) 14086.84,7753.52 14086.84,7738.78 ccw(c14091.84,7738.78) 14096.84,7738.78 14096.84,7753.52 cw(c14101.84,7753.52) 14106.84,7753.52 14106.84,7738.78 ccw(c14111.84,7738.78) 14116.84,7738.78 14116.84,7753.52 cw(c14121.84,7753.52) 14126.84,7753.52 14126.84,7738.78 ccw(c14131.84,7738.78) 14136.84,7738.78 14136.84,7753.52 cw(c14141.84,7753.52) 14141.84,7758.52 v2(14174.29,7758.52)
UP_D12: U5.A7 U8.U3 | length 653.4
  Top Layer w4.7: v2(13773.62,7824.03) U5.A7@13789.37,7839.78
  Top Layer w7.9: v2(14253.04,7679.79) U8.U3@14272.71,7699.47
  L3_SIG1 w5: v2(13773.62,7824.03) 13940.66,7657 14037.01,7657 ccw(c14037.01,7662) 14042.01,7662 14042.01,7666.13 cw(c14047.01,7666.13) 14052.01,7666.13 14052.01,7662 ccw(c14057.01,7662) 14062.01,7662 14062.01,7666.13 cw(c14067.01,7666.13) 14072.01,7666.13 14072.01,7662 ccw(c14077.01,7662) 14077.01,7657 14240.36,7657 14253.04,7669.68 v2(14253.04,7679.79)
UP_D13: U5.A2 U8.U1 | length 648.2
  Top Layer w4.7: U5.A2@13946.85,7839.78 v2(13962.59,7824.03)
  Top Layer w7.9: v2(14174.29,7679.79) U8.U1@14193.96,7699.47
  L6_SIG2 w5: v2(13962.59,7824.03) 13962.59,7740.68 14023.86,7679.41 ccw(c14023.86,7684.41) 14028.86,7684.41 14028.86,7701.83 cw(c14033.86,7701.83) 14038.86,7701.83 14038.86,7684.41 ccw(c14043.86,7684.41) 14048.86,7684.41 14048.86,7701.83 cw(c14053.86,7701.83) 14058.86,7701.83 14058.86,7684.41 ccw(c14063.86,7684.41) 14068.86,7684.41 14068.86,7701.83 cw(c14073.86,7701.83) 14078.86,7701.83 14078.86,7684.41 ccw(c14083.86,7684.41) 14088.86,7684.41 14088.86,7701.83 cw(c14093.86,7701.83) 14098.86,7701.83 14098.86,7684.41 ccw(c14103.86,7684.41) 14108.86,7684.41 14108.86,7701.83 cw(c14113.86,7701.83) 14118.86,7701.83 14118.86,7684.41 ccw(c14123.86,7684.41) 14128.86,7684.41 14128.86,7701.83 cw(c14133.86,7701.83) 14138.86,7701.83 14138.86,7684.41 ccw(c14143.86,7684.41) 14143.86,7679.41 14173.91,7679.41 v2(14174.29,7679.79)
UP_D14: U5.B8 U8.V2 | length 656.8
  Top Layer w4.7: v2(13742.12,7855.53) U5.B8@13757.87,7871.28
  Top Layer w7.9: v2(14213.67,7640.42) U8.V2@14233.34,7660.1
  L3_SIG1 w5: v2(13742.12,7855.53) 13757.38,7840.28 13757.38,7781.98 13913.36,7626 14199.25,7626 v2(14213.67,7640.42)
UP_D15: U5.A3 U8.V1 | length 647
  Top Layer w4.7: U5.A3@13915.35,7839.78 v2(13931.09,7824.03)
  Top Layer w7.9: v2(14174.29,7640.42) U8.V1@14193.96,7660.1
  L6_SIG2 w5: v2(13931.09,7824.03) 13931.09,7700.82 13992,7639.92 14000.05,7639.92 cw(c14000.05,7634.92) 14005.05,7634.92 14005.05,7625.98 ccw(c14010.05,7625.98) 14015.05,7625.98 14015.05,7634.92 cw(c14020.05,7634.92) 14025.05,7634.92 14025.05,7625.98 ccw(c14030.05,7625.98) 14035.05,7625.98 14035.05,7634.92 cw(c14040.05,7634.92) 14045.05,7634.92 14045.05,7625.98 ccw(c14050.05,7625.98) 14055.05,7625.98 14055.05,7634.92 cw(c14060.05,7634.92) 14065.05,7634.92 14065.05,7625.98 ccw(c14070.05,7625.98) 14075.05,7625.98 14075.05,7634.92 cw(c14080.05,7634.92) 14085.05,7634.92 14085.05,7625.98 ccw(c14090.05,7625.98) 14095.05,7625.98 14095.05,7634.92 cw(c14100.05,7634.92) 14105.05,7634.92 14105.05,7625.98 ccw(c14110.05,7625.98) 14115.05,7625.98 14115.05,7634.92 cw(c14120.05,7634.92) 14125.05,7634.92 14125.05,7625.98 ccw(c14130.05,7625.98) 14135.05,7625.98 14135.05,7634.92 cw(c14140.05,7634.92) 14140.05,7639.92 14173.78,7639.92 v2(14174.29,7640.42)
UP_LDM: R188.1 U5.E7 | length 75.5
  Top Layer w4.7: v2(13773.62,7950.02) U5.E7@13789.37,7965.76
  Bottom Layer w7.9: v2(13773.62,7950.02) 13784.6,7939.04 R188.1@13822.36,7939.04
UP_LDQS+: U5.F3 U8.L3 | length 656.7
  Top Layer w4.7: U5.F3@13915.35,7997.26 v2(13931.09,7981.52)
  Top Layer w6.2: v2(14253.04,7955.37) U8.L3@14272.71,7935.7
  L6_SIG2 w3.5: v2(13931.09,7981.52) 13943.23,7993.66 14009.29,7993.66 14010.14,7992.8
  L6_SIG2 w4: 14010.14,7992.8 14014.14,7988.8 14015.34,7988.8
  L6_SIG2 w4.2: 14015.34,7988.8 14042.66,7988.8 14088.6,7942.87 14091.04,7942.87 cw(c14091.04,7937.87) 14096.04,7937.87 14096.04,7922.46 ccw(c14101.04,7922.46) 14106.04,7922.46 14106.04,7937.87 cw(c14111.04,7937.87) 14116.04,7937.87 14116.04,7922.46 ccw(c14121.04,7922.46) 14126.04,7922.46 14126.04,7937.87 cw(c14131.04,7937.87) 14136.04,7937.87 14136.04,7922.46 ccw(c14141.04,7922.46) 14146.04,7922.46 14146.04,7937.87 cw(c14151.04,7937.87) 14156.04,7937.87 14156.04,7922.46 ccw(c14161.04,7922.46) 14166.04,7922.46 14166.04,7937.87 cw(c14171.04,7937.87) 14176.04,7937.87 14176.04,7922.46 ccw(c14181.04,7922.46) 14186.04,7922.46 14186.04,7937.87 cw(c14191.04,7937.87) 14196.04,7937.87 14196.04,7922.46 ccw(c14201.04,7922.46) 14206.04,7922.46 14206.04,7937.87 cw(c14211.04,7937.87) 14211.04,7942.87 14240.54,7942.87 v2(14253.04,7955.37)
UP_LDQS-: U5.G3 U8.L1 | length 652.8
  Top Layer w4.7: U5.G3@13915.35,8028.76 v2(13931.09,8013.02)
  Top Layer w6.2: v2(14174.29,7955.37) U8.L1@14193.96,7935.7
  L6_SIG2 w3.5: v2(13931.09,8013.02) 13943.36,8000.74 14011.35,8000.74
  L6_SIG2 w4: 14011.35,8000.74 14014.61,8004 14015.34,8004
  L6_SIG2 w4.2: 14015.34,8004 14048.96,8004 ccw(c14052.5,8007.54) 14056.03,8004 14062.23,8010.21 cw(c14065.77,8006.67) 14069.3,8003.14 14063.1,7996.93 ccw(c14066.64,7993.4) 14070.17,7989.86 14076.38,7996.07 cw(c14079.91,7992.53) 14083.45,7988.99 14077.24,7982.79 ccw(c14080.78,7979.26) 14084.31,7975.72 14090.52,7981.92 cw(c14094.05,7978.39) 14097.59,7974.85 14091.39,7968.65 ccw(c14094.92,7965.11) 14091.39,7961.58 14094.89,7958.07 14105.91,7958.07 ccw(c14105.91,7963.07) 14110.91,7963.07 14110.91,7995.3 cw(c14115.91,7995.3) 14120.91,7995.3 14120.91,7963.07 ccw(c14125.91,7963.07) 14130.91,7963.07 14130.91,7995.3 cw(c14135.91,7995.3) 14140.91,7995.3 14140.91,7963.07 ccw(c14145.91,7963.07) 14150.91,7963.07 14150.91,7995.3 cw(c14155.91,7995.3) 14160.91,7995.3 14160.91,7976 14178.16,7976 14184.36,7969.8 14184.36,7959 14180.36,7955 14174.66,7955 v2(14174.29,7955.37)
UP_ODT: R29.1 U5.K1 U8.J6 | length 1179.9
  Top Layer w4.7: v3(13963.36,8457) 13963.36,8431 14065.36,8329 14065.36,8210.26 v2(13994.08,8138.98) U5.K1@13978.34,8123.24
  Top Layer w7.9: v2(14371.15,8034.1) U8.J6@14390.82,8014.43
  Bottom Layer w4.7: R29.1@13946.36,8486.96 13946.36,8474 v3(13963.36,8457) ; v2(13994.08,8138.98) 14039.04,8138.98 cw(c14035.5,8135.45) 14039.04,8131.91 14033.59,8126.47 ccw(c14037.13,8122.94) 14040.67,8119.4 14046.11,8124.84 cw(c14049.64,8121.31) 14053.18,8117.77 14047.74,8112.33 ccw(c14051.27,8108.79) 14054.81,8105.26 14060.25,8110.7 cw(c14063.79,8107.17) 14067.32,8103.63 14061.88,8098.19 ccw(c14065.41,8094.65) 14068.95,8091.12 14074.39,8096.56 cw(c14077.93,8093.02) 14081.46,8089.49 14076.02,8084.05 ccw(c14079.56,8080.51) 14083.09,8076.97 14088.53,8082.42 cw(c14092.07,8078.88) 14095.61,8082.42 14128.38,8049.65 cw(c14128.38,8044.65) 14133.38,8044.65 14133.38,7987.73 ccw(c14138.38,7987.73) 14143.38,7987.73 14143.38,8044.65 cw(c14148.38,8044.65) 14148.38,8049.65 14218.77,8049.65 14252.75,8015.66 14303.31,8015.66
  Bottom Layer w7.9: 14303.51,8015.75 14312.04,8024.28 14312.04,8044.59 14322.52,8055.07 14360.01,8055.07 14371.15,8043.94 v2(14371.15,8034.1)
UP_RAS: R27.1 U5.J3 U8.K5 | length 1337.8
  Top Layer w4.7: R27.1@13706.36,8486.96 13706.36,8481 13721.36,8466 13721.36,8407 13724.36,8404 13776.68,8404 13829.36,8351.32 13829.36,8118 13855.61,8091.75 U5.J3@13915.35,8091.75 v2(13931.09,8107.49)
  Top Layer w7.9: v2(14331.79,7994.73) U8.K5@14351.46,7975.06
  Bottom Layer w4.7: v2(13931.09,8107.49) 13946.35,8122.75 13966.79,8122.75 14026.54,8063 14076.4,8063 14101.61,8037.79 14101.61,7977.39 cw(c14098.07,7973.86) 14101.61,7970.32 14094.49,7963.21 ccw(c14098.02,7959.67) 14101.56,7956.13 14108.68,7963.25 cw(c14112.21,7959.72) 14115.75,7956.18 14108.63,7949.06 ccw(c14112.17,7945.53) 14115.7,7941.99 14122.82,7949.11 cw(c14126.35,7945.57) 14129.89,7942.04 14122.77,7934.92 ccw(c14126.31,7931.39) 14129.84,7927.85 14136.96,7934.97 cw(c14140.5,7931.43) 14144.03,7934.97 14176.65,7902.35 14330.36,7902.35 14351.37,7923.36 14351.37,7982.29 14338.93,7994.73 v2(14331.79,7994.73)
UP_RST: R2.1 U5.T2 U8.C3 | length 819.9
  Top Layer w4.7: U5.T2@13946.85,8312.22 v2(13962.59,8327.97)
  Top Layer w7.9: v2(14253.04,8270.32) U8.C3@14272.71,8250.65
  L6_SIG2 w5: v2(13962.59,8327.97) 13981.9,8347.28 ccw(c13981.9,8352.28) 13986.9,8352.28 13986.9,8375.5 cw(c13991.9,8375.5) 13996.9,8375.5 13996.9,8352.28 ccw(c14001.9,8352.28) 14006.9,8352.28 14006.9,8375.5 cw(c14011.9,8375.5) 14016.9,8375.5 14016.9,8352.28 ccw(c14021.9,8352.28) 14026.9,8352.28 14026.9,8375.5 cw(c14031.9,8375.5) 14036.9,8375.5 14036.9,8352.28 ccw(c14041.9,8352.28) 14046.9,8352.28 14046.9,8375.5 cw(c14051.9,8375.5) 14056.9,8375.5 14056.9,8352.28 ccw(c14061.9,8352.28) 14066.9,8352.28 14066.9,8375.5 cw(c14071.9,8375.5) 14076.9,8375.5 14076.9,8352.28 ccw(c14081.9,8352.28) 14086.9,8352.28 14086.9,8375.5 cw(c14091.9,8375.5) 14096.9,8375.5 14096.9,8352.28 ccw(c14101.9,8352.28) 14106.9,8352.28 14106.9,8375.5 cw(c14111.9,8375.5) 14116.9,8375.5 14116.9,8352.28 ccw(c14121.9,8352.28) 14121.9,8347.28 14139.49,8347.28 14193.52,8293.25 14232.38,8293.25 14253.04,8272.59 v2(14253.04,8270.32)
  Bottom Layer w6: R2.1@13950.32,8356 13950.32,8340.24 v2(13962.59,8327.97)
UP_UDM: R189.1 U5.D3 | length 113.8
  Top Layer w4.7: U5.D3@13915.35,7934.27 v2(13931.09,7918.52)
  Bottom Layer w6: R189.1@13881.36,7975.96 13904.4,7975.96 13915.36,7965 13915.36,7934.26 v2(13931.09,7918.52)
UP_UDQS+: U5.C7 U8.T2 | length 655.2
  Top Layer w4.7: v2(13773.62,7887.02) U5.C7@13789.37,7902.77
  Top Layer w6.2: v2(14213.67,7719.16) U8.T2@14233.34,7738.84
  L3_SIG1 w4.2: v2(13773.62,7887.02) 13783.62,7887.02 13791.77,7878.88 13801.16,7878.88 13938.2,7741.84 14030.98,7741.84 ccw(c14030.98,7746.84) 14035.98,7746.84 14035.98,7752.39 cw(c14040.98,7752.39) 14045.98,7752.39 14045.98,7746.84 ccw(c14050.98,7746.84) 14055.98,7746.84 14055.98,7752.39 cw(c14060.98,7752.39) 14065.98,7752.39 14065.98,7746.84 ccw(c14070.98,7746.84) 14075.98,7746.84 14075.98,7752.39 cw(c14080.98,7752.39) 14085.98,7752.39 14085.98,7746.84 ccw(c14090.98,7746.84) 14095.98,7746.84 14095.98,7752.39 cw(c14100.98,7752.39) 14105.98,7752.39 14105.98,7746.84 ccw(c14110.98,7746.84) 14110.98,7741.84 14190.48,7741.84 14201.58,7730.75 14201.58,7721.35 14203.77,7719.16 v2(14213.67,7719.16)
UP_UDQS-: U5.B7 U8.T1 | length 653.3
  Top Layer w4.7: v2(13773.62,7855.53) U5.B7@13789.37,7871.28
  Top Layer w6.2: v2(14174.29,7719.16) U8.T1@14193.96,7738.84
  L3_SIG1 w4.2: v2(13773.62,7855.53) 13783.62,7855.53 13791.77,7863.68 13794.87,7863.68 13931.9,7726.64 13953.34,7726.64 cw(c13953.34,7721.64) 13958.34,7721.64 13958.34,7708.47 ccw(c13963.34,7708.47) 13968.34,7708.47 13968.34,7721.64 cw(c13973.34,7721.64) 13978.34,7721.64 13978.34,7708.47 ccw(c13983.34,7708.47) 13988.34,7708.47 13988.34,7721.64 cw(c13993.34,7721.64) 13998.34,7721.64 13998.34,7708.47 ccw(c14003.34,7708.47) 14008.34,7708.47 14008.34,7721.64 cw(c14013.34,7721.64) 14013.34,7726.64 14184.18,7726.64 14186.38,7724.45 14186.38,7721.35 14184.18,7719.16 v2(14174.29,7719.16)
UP_WE: R32.1 U5.L3 U8.F2 | length 1018.1
  Top Layer w4.7: v3(13761.36,8461) 13761.36,8437 13769.36,8429 13799.51,8429 13853.36,8375.15 13853.36,8171 13869.62,8154.74 U5.L3@13915.35,8154.74 v2(13931.09,8170.48)
  Top Layer w7.9: v2(14213.67,8152.21) U8.F2@14233.34,8132.53
  L6_SIG2 w5: v2(13931.09,8170.48) 13948.69,8152.89 13974.3,8152.89 ccw(c13974.3,8157.89) 13979.3,8157.89 13979.3,8168.14 cw(c13984.3,8168.14) 13989.3,8168.14 13989.3,8157.89 ccw(c13994.3,8157.89) 13994.3,8152.89 13998.87,8152.89 14021.09,8130.67 ccw(c14021.09,8135.67) 14026.09,8135.67 14026.09,8145.08 cw(c14031.09,8145.08) 14036.09,8145.08 14036.09,8135.67 ccw(c14041.09,8135.67) 14046.09,8135.67 14046.09,8145.08 cw(c14051.09,8145.08) 14056.09,8145.08 14056.09,8135.67 ccw(c14061.09,8135.67) 14066.09,8135.67 14066.09,8145.08 cw(c14071.09,8145.08) 14076.09,8145.08 14076.09,8135.67 ccw(c14081.09,8135.67) 14086.09,8135.67 14086.09,8145.08 cw(c14091.09,8145.08) 14096.09,8145.08 14096.09,8135.67 ccw(c14101.09,8135.67) 14106.09,8135.67 14106.09,8145.08 cw(c14111.09,8145.08) 14116.09,8145.08 14116.09,8135.67 ccw(c14121.09,8135.67) 14126.09,8135.67 14126.09,8145.08 cw(c14131.09,8145.08) 14136.09,8145.08 14136.09,8135.67 ccw(c14141.09,8135.67) 14141.09,8130.67 14192.12,8130.67 v2(14213.67,8152.21)
  Bottom Layer w4.7: R32.1@13746.36,8486.96 13761.36,8471.96 v3(13761.36,8461)
USB_5V: D26.1 D30.1 F3.2 R157.2 USB4.2 USB4.11 | length 1384.5
  Top Layer w10: R157.2@13289.73,6600.56 13290.36,6599.93 v3(13290.36,6571)
  Top Layer w30: USB4.11@12778.52,5878.74 12821.85,5878.74 12864.02,5920.91 12864.02,5925.26 v1@12864.57,5925.8 ; USB4.2@12784.53,6067.93 12833.86,6067.93 v1@12864.43,6037.36
  L6_SIG2 w10: v1(12839.95,5899.02) 12840.28,5898.69 12919.39,5898.69 12919.39,5984.77 13290.36,6355.74 v3(13290.36,6572)
  Bottom Layer w10: v3(13290.36,6571) v3(13290.36,6572)
  Bottom Layer w20: D30.1@12865.67,5961.25 D26.1@12969.61,5961.25 ; D26.1@12970.67,5960.19 D26.1@12969.61,5961.25 ; F3.2@13105.67,5973.2 13093.72,5961.25 D26.1@12969.61,5961.25
  other v1: 12863.87,5924.29 12865.38,6036.17 12846.36,6056.01
USER_KEY: R150.1 SW3.1 U8.V11 | length 2669.5
  Top Layer w4.7: v3(12672.36,8272) 12733.25,8272 SW3.1@12734.25,8271 ; v3(14567.36,7638) 14587.66,7658.3 U8.V11@14587.66,7660.1
  L6_SIG2 w5: v3(12672.36,8272) 12672.66,8272.3 12738.43,8272.3 12760.36,8250.37 12760.36,8083 13260.36,7583 14184.36,7583 14195.36,7594 14195.36,7609 14206.36,7620 14215.36,7620 14231.36,7636 14231.36,7766 14243.36,7778 14489.36,7778 14547.36,7720 14547.36,7658 v3(14567.36,7638)
  Bottom Layer w4.7: R150.1@12634.4,8272 v3(12672.36,8272)
USER_KEY1: R168.1 SW4.1 U8.U10 | length 2437.1
  Top Layer w4.7: v3(12671.36,7926) SW4.1@12734.25,7926 ; v3(14529.36,7677) 14548.3,7695.94 U8.U10@14548.3,7699.47
  L6_SIG2 w5: v3(12671.36,7926) 12718.36,7926 12780.36,7864 12780.36,7724 12967.36,7537 14188.36,7537 14235.36,7584 14235.36,7612 14241.36,7618 14266.36,7618 14273.36,7625 14273.36,7733 14278.36,7738 14464.36,7738 14468.36,7734 14468.36,7704 14473.36,7699 14507.36,7699 v3(14529.36,7677)
  Bottom Layer w4.7: R168.1@12634.4,7926 v3(12671.36,7926)
USER_KEY2: R169.1 SW5.1 U8.T15 | length 2577.1
  Top Layer w4.7: v3(12667.36,7602) 12728.25,7602 SW5.1@12729.25,7601 ; U8.T15@14745.16,7738.84 14748.52,7738.84 v3(14764.36,7723)
  L3_SIG1 w5: v3(12667.36,7602) 12667.36,7596 12688.83,7574.53 14287.89,7574.53 14305.36,7592 14305.36,7792 14365.36,7852 14735.46,7852 14743.36,7844.1 14743.36,7744 v3(14764.36,7723)
  Bottom Layer w4.7: R169.1@12634.4,7602 v3(12667.36,7602)
USER_LED: Q16.1 R149.2 U8.R13 | length 2482.8
  Top Layer w4.7: U8.R13@14666.41,7778.2 14686.36,7758.25 v3(14686.36,7756)
  L3_SIG1 w5: v3(12689.36,7425) 13151.36,7425 13262.36,7536 14291.36,7536 14318.94,7563.58 14318.94,7780.58 14362.36,7824 14658.36,7824 14665.36,7817 14665.36,7777 v3(14686.36,7756)
  Bottom Layer w4.7: Q16.1@12674.96,7320.37 12674.96,7365.64 R149.2@12690.32,7381 12689.36,7381.96 v3(12689.36,7425)
VCC_1V2: C5.2 C6.2 C7.2 C8.2 C9.2 C10.2 C11.2 C12.2 C13.2 C14.2 C15.2 C16.2 C207.2 C293.2 C294.2 C295.2 C296.2 C297.2 C298.2 C299.2 C300.2 C301.2 C302.2 L27.2 U8.J8 U8.J10 U8.J12 U8.J14 U8.K9 U8.K11 U8.K13 U8.L10 U8.L12 U8.L14 U8.M9 U8.M11 U8.M13 U8.N10 U8.N12 U8.N14 U8.P9 U8.P11 U8.P13 U8.R14 U74.1 | length 2786.2
  Top Layer w10: U74.1@14114.83,10802.21 14115.83,10801.22 v3(14115.83,10741.94) ; v2(14449.89,8034.1) U8.J8@14469.56,8014.43 ; v2(14489.26,7797.9) U8.P9@14508.93,7817.57 ; v2(14489.26,7876.62) U8.M9@14508.93,7896.3 ; v2(14489.26,7994.73) U8.K9@14508.93,7975.06 ; v2(14528.63,7837.27) U8.N10@14548.3,7856.94 ; v2(14528.63,7955.37) U8.L10@14548.3,7935.7 ; v2(14528.63,8034.1) U8.J10@14548.3,8014.43 ; v2(14567.99,7797.9) U8.P11@14587.66,7817.57 ; v2(14567.99,7876.62) U8.M11@14587.66,7896.3 ; v2(14567.99,7994.73) U8.K11@14587.66,7975.06 ; U8.N12@14627.06,7856.94 v2(14646.74,7837.27) ; U8.L12@14627.06,7935.7 v2(14646.74,7955.37) ; U8.J12@14627.06,8014.43 v2(14646.74,8034.1) ; U8.P13@14666.41,7817.57 v2(14686.09,7797.9) ; U8.M13@14666.41,7896.3 v2(14686.09,7876.62) ; U8.K13@14666.41,7975.06 v2(14686.09,7994.73) ; U8.R14@14705.78,7778.2 v2(14725.46,7758.52) ; U8.N14@14705.78,7856.94 v2(14725.46,7837.27) ; U8.L14@14705.78,7935.7 v2(14725.46,7955.37) ; U8.J14@14705.78,8014.43 v2(14725.46,8034.1)
  L3_SIG1 w10: v3(14114.83,10738.46) 14114.83,10606.46 14121.81,10599.48 14187.43,10599.48 15021.53,9765.39 v1(15095.6,9765.39)
  L5_PWR w10: v2(14449.89,8034.1) v2(14489.26,7994.73)
  Bottom Layer w6: v2(14449.89,8034.1) 14467.36,8016.63 C11.2@14467.36,8014.54 ; v2(14489.26,7797.9) 14491.12,7797.9 C7.2@14508.65,7815.43 ; v2(14489.26,7876.62) 14508.38,7895.74 C12.2@14508.38,7895.99 ; v2(14489.26,7994.73) 14507.36,7976.63 C302.2@14507.36,7974.54 ; v2(14528.63,7837.27) 14529.76,7837.27 C293.2@14547.82,7855.33 ; v2(14528.63,7955.37) 14528.63,7952.15 C294.2@14546.62,7934.16 ; v2(14528.63,8034.1) C10.2@14546.62,8016.11 ; v2(14567.99,7797.9) 14570.72,7797.9 C14.2@14587.36,7814.54 ; v2(14567.99,7876.62) 14569.44,7876.62 C299.2@14587.36,7894.54 ; v2(14567.99,7994.73) 14587.36,7975.36 C301.2@14587.36,7974.54 ; C8.2@14627.36,7857.46 14646.74,7838.08 v2(14646.74,7837.27) ; C298.2@14627.36,7937.46 14628.83,7937.46 v2(14646.74,7955.37) ; C15.2@14627.36,8017.46 14630.1,8017.46 v2(14646.74,8034.1) ; C296.2@14666.9,7815.48 14668.51,7815.48 v2(14686.09,7797.9) ; C295.2@14667.36,7894.54 14668.17,7894.54 v2(14686.09,7876.62) ; C16.2@14705.9,7776 14707.98,7776 v2(14725.46,7758.52)
  Bottom Layer w10: v3(14114.83,10738.46) 14114.83,10740.95 v3(14115.83,10741.94) ; C300.2@14667.36,7974.54 14686.09,7993.27 v2(14686.09,7994.73) ; C13.2@14707.36,7857.46 14725.46,7839.36 v2(14725.46,7837.27) ; C297.2@14707.36,7937.46 14707.55,7937.46 v2(14725.46,7955.37) ; C9.2@14707.36,8017.46 14708.82,8017.46 v2(14725.46,8034.1)
  Bottom Layer w30: C6.2@15014.92,8411 15017.1,8413.18 C5.2@15017.1,8521
  other v1: 14924.36,8632 14924.36,8663 14957.36,8663 14957.36,8693 14925.36,8694 14988.36,8695 15060.4,9709.76 15060.52,9736.85 15096.48,9737.87 15059.75,9764.69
